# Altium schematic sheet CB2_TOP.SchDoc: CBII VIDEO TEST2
size A4; Engineer: SHOWELL; DocumentNumber: 1; Revision: 1.00; SheetNumber: 1; SheetTotal: 1; PageSetup: Record=PageOptions|CenterHorizontal=True|CenterVertical=True|PrintScale=1.47|XCorrection=1.00|YCorrection=1.00|PrintKind=0|BorderSize=5000000|LeftOffset=0|BottomOffset=0|Orientation=2|PaperLength=1000|PaperWidth=1000|Scale=100|PaperSource=7|PrintQuality=-4|MediaType=1|DitherType=10|PaperKind=A2|PrintScaleMode=1
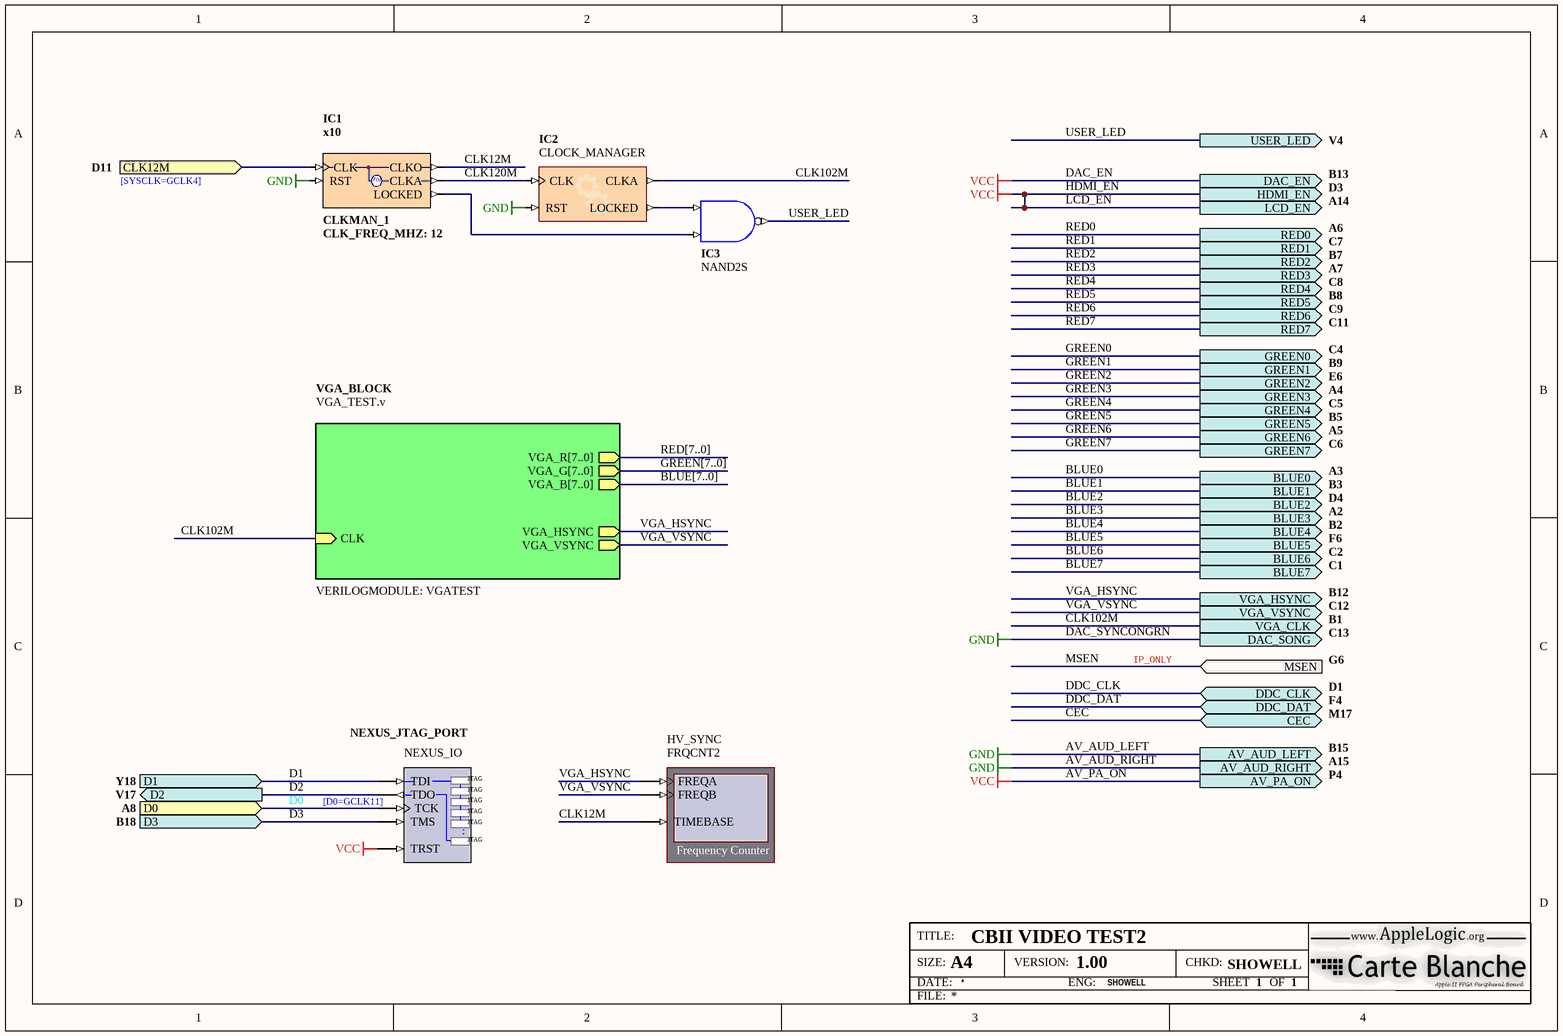
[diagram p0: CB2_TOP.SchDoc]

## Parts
HV_SYNC  FRQCNT2
IC1  CLKMAN_1  CLK_FREQ_MHZ: 12  ClkA_Operation: x10
IC2  CLOCK_MANAGER
IC3  NAND2S
NEXUS_JTAG_PORT  NEXUS_IO

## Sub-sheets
VGA_BLOCK = VGA_TEST.v: CLK (in), VGA_B[7..0] (out), VGA_G[7..0] (out), VGA_HSYNC (out), VGA_R[7..0] (out), VGA_VSYNC (out)  | VERILOGMODULE: VGATEST

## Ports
AV_AUD_LEFT (out, see B15), AV_AUD_RIGHT (out, see A15), AV_PA_ON (out, see P4), BLUE0 (out, see A3), BLUE1 (out, see B3), BLUE2 (out, see D4), BLUE3 (out, see A2), BLUE4 (out, see B2), BLUE5 (out, see F6), BLUE6 (out, see C2), BLUE7 (out, see C1), CEC (bidir, see M17), CLK12M (in, see D11), D0 (in, see A8), D1 (in, see Y18), D2 (out, see V17), D3 (in, see B18), DAC_EN (out, see B13), DAC_SONG (out, see C13), DDC_CLK (bidir, see D1), DDC_DAT (bidir, see F4), GREEN0 (out, see C4), GREEN1 (out, see B9), GREEN2 (out, see E6), GREEN3 (out, see A4), GREEN4 (out, see C5), GREEN5 (out, see B5), GREEN6 (out, see A5), GREEN7 (out, see C6), HDMI_EN (out, see D3), LCD_EN (out, see A14), MSEN (in, see G6), RED0 (out, see A6), RED1 (out, see C7), RED2 (out, see B7), RED3 (out, see A7), RED4 (out, see C8), RED5 (out, see B8), RED6 (out, see C9), RED7 (out, see C11), USER_LED (out, see V4), VGA_CLK (out, see B1), VGA_HSYNC (out, see B12), VGA_VSYNC (out, see C12)

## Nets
AV_AUD_LEFT: IC1.RST IC2.RST ; port DAC_SONG, port AV_AUD_LEFT, port AV_AUD_RIGHT  [also labelled AV_AUD_RIGHT, DAC_SYNCONGRN, GND]
AV_PA_ON: NEXUS_JTAG_PORT.TRST ; port HDMI_EN, port AV_PA_ON, port DAC_EN, port LCD_EN  [also labelled DAC_EN, HDMI_EN, LCD_EN, VCC]
CLK12M: IC1.CLK ; port CLK12M
CLK12M: HV_SYNC.TIMEBASE IC1.CLKO  [a separate net that carries the same name]
CLK102M: IC2.CLKA ; port VGA_CLK, sheet VGA_BLOCK/CLK
CLK120M: IC1.CLKA IC2.CLK
D0: NEXUS_JTAG_PORT.TCK ; port D0
D1: NEXUS_JTAG_PORT.TDI ; port D1
D2: NEXUS_JTAG_PORT.TDO ; port D2
D3: NEXUS_JTAG_PORT.TMS ; port D3
USER_LED: IC3.O ; port USER_LED
VGA_HSYNC: HV_SYNC.FREQA ; port VGA_HSYNC, sheet VGA_BLOCK/VGA_HSYNC
VGA_VSYNC: HV_SYNC.FREQB ; port VGA_VSYNC, sheet VGA_BLOCK/VGA_VSYNC
NetIC1_LOCKED: IC1.LOCKED IC3.I1
NetIC2_LOCKED: IC2.LOCKED IC3.I0

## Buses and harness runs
bus BLUE[7..0] = sheet VGA_BLOCK/VGA_B[7..0]
bus GREEN[7..0] = sheet VGA_BLOCK/VGA_G[7..0]
bus RED[7..0] = sheet VGA_BLOCK/VGA_R[7..0]

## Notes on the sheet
- [SYSCLK=GCLK4]
- IP_ONLY
- (near NEXUS_JTAG_PORT) [D0=GCLK11]

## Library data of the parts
HV_SYNC = FRQCNT2: Frequency Counter; NEXUS_CORE: Instrument; NEXUS_JTAG_DEVICE: True; NEXUS_JTAG_ORDER: 0
IC1 = CLKMAN_1: Single Operational Output Clock Manager; Clk_Count: 1
IC2 = CLOCKMANAGER: Configurable Clock Manager; ConfiguratorName: GENERIC_CLOCKMANAGER; ConfigurationParameters: {}Version[1.0]{}Option_Configuration[object _1: TClockManagerPersist / VersionMajor [ 0 / VersionMinor [ 0 / InputFreq [ 120.000000000000000000 / InputName [ 'CLK' / OutputTargets [ < / item / Name [ 'CLKA' / OutFreqMin [ 102.000000000000000000 / OutFreqMax [ 102.000000000000000000 / OutPostDivider [ 1.000000000000000000 / end> / OutputDevices [ < / item / Name [ 'Spartan3AN' / Valid [ True / OutputActuals [ < / item / Name [ 'CLK0' / Multipler [ 1.000000000000000000 / Divider [ 1.000000000000000000 / OutFreq [ 120.000000000000000000 / OutputMap [ 1 / end / item / Name [ 'CLK90' / Multipler [ 1.000000000000000000 / Divider [ 1.000000000000000000 / OutPhase [ 90.000000000000000000 / OutFreq [ 120.000000000000000000 / OutputMap [ 2 / end / item / Name [ 'CLK180' / Multipler [ 1.000000000000000000 / Divider [ 1.000000000000000000 / OutPhase [ 180.000000000000000000 / OutFreq [ 120.000000000000000000 / OutputMap [ 3 / end / item / Name [ 'CLK270' / Multipler [ 1.000000000000000000 / Divider [ 1.000000000000000000 / OutPhase [ 270.000000000000000000 / OutFreq [ 120.000000000000000000 / OutputMap [ 4 / end / item / Name [ 'CLK2X' / Multipler [ 2.000000000000000000 / Divider [ 1.000000000000000000 / OutFreq [ 240.000000000000000000 / OutputMap [ 5 / end / item / Name [ 'CLKDV' / Multipler [ 1.000000000000000000 / Divider [ 16.000000000000000000 / OutFreq [ 7.500000000000000000 / OutputMap [ 6 / end / item / Name [ 'CLK2X180' / Multipler [ 1.000000000000000000 / Divider [ 1.000000000000000000 / OutPhase [ 180.000000000000000000 / OutFreq [ 240.000000000000000000 / OutputMap [ 7 / end / item / Name [ 'CLKFX' / Multipler [ 17.000000000000000000 / Divider [ 20.000000000000000000 / OutFreq [ 102.000000000000000000 / OutputMap [ 0 / end / item / Name [ 'CLKFX180' / Multipler [ 1.000000000000000000 / Divider [ 1.000000000000000000 / OutPhase [ 180.000000000000000000 / OutFreq [ 102.000000000000000000 / OutputMap [ 8 / end> / InternalActuals [ <> / CustomVars [ <> / end> / MinInputFreq [ 1.000000000000000000 / MaxInputFreq [ 280.000000000000000000 / MinOutputFreq [ 18.000000000000000000 / MaxOutputFreq [ 210.000000000000000000 / MaxOutputCount [ 9 / end]{}
IC3 = NAND2S: 2-Input NAND Gate, Single Pin Version; XilinxEquivalent: NAND2; FunctionalClass: Logic Primitive; PortSize: 2; ArchiveName: GENERIC; VHDLIB_SIM: GENERIC_LIB
NEXUS_JTAG_PORT = NEXUS_JTAG_PORT: Soft Nexus-Chain Connector; NEXUS_JTAG_CONNECTOR: True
